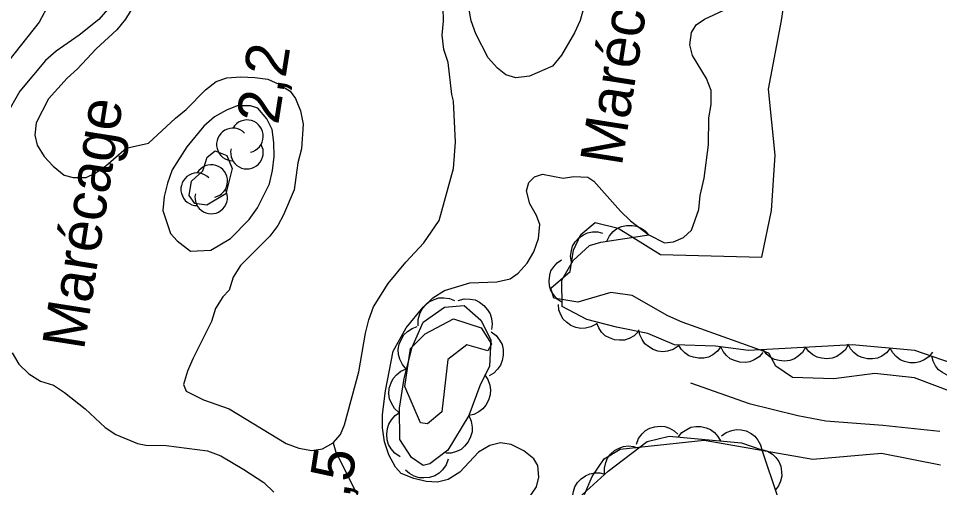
# Model space of a CAD drawing. Extents: x 282461 to 284471, y 5554090 to 5557646.
# Drawn here: x 283387.5 to 283452.6, y 5555299.8 to 5555332.9 of the extents above; entities that cross this region are included whole.
import ezdxf

# ---------------------------------------------------------------- set-up
doc = ezdxf.new("R2010")
doc.units = 0
for name, color, linetype in [('Niveau 2', 7, 'Continuous'), ('Niveau 22', 7, 'Continuous'), ('Niveau 3', 7, 'Continuous'), ('Niveau 4', 7, 'Continuous'), ('Niveau 44', 7, 'Continuous'), ('Niveau 7', 7, 'Continuous')]:
    doc.layers.add(name, color=color, linetype=linetype)

msp = doc.modelspace()

# ---------------------------------------------------------------- linework, layer by layer
at = {"layer": 'Niveau 2'}
for points in [[(283387.21, 5555348), (283388.34, 5555344.06), (283389.27, 5555342.21), (283389.76, 5555339.91), (283390.28, 5555336.74), (283389.69, 5555333.93), (283389.01, 5555332.65), (283385.14, 5555327.79)], [(283433.42, 5555311.91), (283430.9, 5555313.34), (283429.39, 5555313.55), (283427.06, 5555312.87), (283425.38, 5555313.15), (283425.15, 5555313.87), (283426.53, 5555315.03), (283426.77, 5555316.54), (283427.28, 5555317.66), (283428.28, 5555318.5), (283429.92, 5555318.1), (283432.9, 5555316.25), (283440.06, 5555316.05), (283440.76, 5555319.34), (283441, 5555323.25), (283440.53, 5555327.92), (283441.46, 5555332.77), (283442.2, 5555337.61)], [(283400.84, 5555319.72), (283400.01, 5555319.84), (283399.59, 5555320.41), (283399.77, 5555321.41), (283400.56, 5555322.14), (283400.87, 5555323.12), (283401.44, 5555323.56), (283402.26, 5555323.24), (283402.65, 5555322.32), (283402.2, 5555320.52), (283400.84, 5555319.72)], [(283416.44, 5555304.27), (283415.95, 5555304.34), (283414.83, 5555306.91), (283415.24, 5555309.6), (283416.28, 5555310.63), (283418.28, 5555311.69), (283420.24, 5555311.05), (283420.96, 5555309.9), (283420.71, 5555309.44), (283419.23, 5555309.85), (283417.87, 5555308.83), (283417.46, 5555305.13), (283416.44, 5555304.27)], [(283440.56, 5555309.27), (283434.43, 5555311.47), (283433.42, 5555311.91)], [(283471.91, 5555297.48), (283473.89, 5555297.67), (283474.58, 5555298.25), (283474.92, 5555299.07), (283474.33, 5555299.76), (283472.46, 5555300.32), (283463.13, 5555302.2), (283459.86, 5555303.32), (283456.23, 5555305.26), (283453.54, 5555306.51), (283450.85, 5555307.53), (283448.06, 5555307.84), (283445.15, 5555307.46), (283442.24, 5555307.55), (283441.07, 5555308.35), (283440.56, 5555309.27)], [(283427.53, 5555299.29), (283428.07, 5555300.57), (283428.93, 5555301.81), (283430.07, 5555302.5), (283435.99, 5555303.12), (283443.68, 5555301.78), (283448.53, 5555302.21), (283452.7, 5555301.38)]]:
    msp.add_lwpolyline(points, dxfattribs=at)
at = {"layer": 'Niveau 22'}
msp.add_lwpolyline([(283435.03, 5555307.18), (283439.18, 5555305.72), (283442.62, 5555304.88), (283444.6, 5555304.5), (283448.62, 5555304.19), (283452.64, 5555303.77)], dxfattribs=at)
at = {"layer": 'Niveau 4'}
for points in [[(283396.08, 5555334.51), (283395.11, 5555332.87), (283394.48, 5555332.11), (283393.04, 5555330.76), (283391.72, 5555329.35), (283390.97, 5555328.7), (283389.65, 5555327.23), (283388.8, 5555325.54), (283388.69, 5555324.67), (283388.87, 5555323.97), (283389.35, 5555323.16), (283390, 5555322.47), (283390.76, 5555321.84), (283391.4, 5555321.67), (283392.33, 5555321.68), (283392.97, 5555321.98), (283393.72, 5555322.51), (283395.16, 5555323.75), (283396.73, 5555324.11), (283398.63, 5555325.88), (283399.38, 5555326.47), (283400.76, 5555327.88), (283401.5, 5555328.47), (283402.26, 5555328.71), (283403.25, 5555328.78), (283404.24, 5555328.73)], [(283407.55, 5555323.71), (283407.27, 5555322.72), (283407.01, 5555320.8), (283406.27, 5555319.05), (283405.87, 5555318.29), (283405.3, 5555317.53), (283403.23, 5555315.47), (283402.71, 5555314.65), (283402.43, 5555313.72), (283401.97, 5555313.25), (283401.46, 5555312.43), (283401.18, 5555311.5), (283399.87, 5555308.87), (283399.48, 5555307.99), (283399.2, 5555307.06), (283399.38, 5555306.59), (283400.61, 5555305.97), (283402.42, 5555305.35), (283406.46, 5555302.89), (283407.34, 5555302.56), (283408.27, 5555302.39), (283409.03, 5555302.52), (283409.78, 5555302.93), (283410.29, 5555303.52), (283410.58, 5555304.22), (283411.58, 5555307.95), (283412.07, 5555310.68), (283412.29, 5555311.62), (283412.63, 5555312.55), (283413.66, 5555314.19), (283414.92, 5555315.71), (283416.19, 5555317.06), (283417.27, 5555318.64), (283418.28, 5555322.32), (283418.43, 5555324.18), (283418.28, 5555327.08), (283418.16, 5555327.54), (283417.9, 5555329.81), (283417.6, 5555330.73), (283417.47, 5555331.72), (283417.57, 5555332.71), (283417.56, 5555333.7)], [(283404.24, 5555328.73), (283405.17, 5555328.62), (283405.93, 5555328.28), (283406.75, 5555327.77), (283407.11, 5555327.25), (283407.46, 5555326.38), (283407.65, 5555325.45), (283407.55, 5555323.71)], [(283409.78, 5555302.93), (283409.96, 5555302.29), (283411.86, 5555298.54), (283412.46, 5555297.15), (283412.89, 5555295.76), (283413.08, 5555294.42), (283412.99, 5555292.33), (283412.35, 5555286.63), (283411.96, 5555285.4), (283410.88, 5555283.48), (283408.75, 5555280.95), (283407.26, 5555279.54), (283404.77, 5555278.3)]]:
    msp.add_lwpolyline(points, dxfattribs=at)
at = {"layer": 'Niveau 44'}
for points in [[(283429.12, 5555317.18), (283429.3, 5555317.56), (283429.57, 5555317.86), (283429.83, 5555318.07), (283430.15, 5555318.21), (283430.51, 5555318.3), (283430.9, 5555318.29), (283431.22, 5555318.25), (283431.54, 5555318.1), (283431.85, 5555317.89), (283432.09, 5555317.62)], [(283489.79, 5555302.45), (283483.29, 5555301.45), (283476.78, 5555301.15), (283470.5, 5555301.78), (283465.37, 5555303.11), (283454.15, 5555308.33), (283450.88, 5555309.46), (283446.46, 5555309.87), (283439.13, 5555309.46), (283436.8, 5555309.76), (283433.89, 5555309.87), (283432.02, 5555310.66), (283429.81, 5555311.1), (283427.71, 5555311.66), (283425.96, 5555312.56), (283425.93, 5555314.42), (283426.73, 5555315.82), (283427.88, 5555316.88), (283428.69, 5555317.12), (283432.09, 5555317.62)], [(283426.61, 5555315.71), (283426.55, 5555316.12), (283426.61, 5555316.53), (283426.7, 5555316.84), (283426.89, 5555317.14), (283427.14, 5555317.41), (283427.46, 5555317.62), (283427.75, 5555317.77), (283428.1, 5555317.83), (283428.47, 5555317.83), (283428.82, 5555317.75)], [(283425.96, 5555312.86), (283425.6, 5555313.09), (283425.34, 5555313.41), (283425.17, 5555313.69), (283425.07, 5555314.02), (283425.03, 5555314.39), (283425.09, 5555314.77), (283425.17, 5555315.09), (283425.36, 5555315.38), (283425.61, 5555315.66), (283425.91, 5555315.87)], [(283415.79, 5555311.21), (283415.79, 5555311.64), (283415.9, 5555312.04), (283416.04, 5555312.36), (283416.27, 5555312.64), (283416.56, 5555312.89), (283416.92, 5555313.06), (283417.24, 5555313.17), (283417.6, 5555313.18), (283417.99, 5555313.13), (283418.34, 5555313)], [(283418.62, 5555313), (283419.04, 5555313.11), (283419.46, 5555313.09), (283419.8, 5555313.04), (283420.12, 5555312.87), (283420.43, 5555312.65), (283420.69, 5555312.34), (283420.87, 5555312.06), (283420.97, 5555311.71), (283421.01, 5555311.32), (283420.96, 5555310.95)], [(283419.36, 5555304.86), (283417.87, 5555302.41), (283416.61, 5555301.46), (283416.14, 5555301.34), (283415.32, 5555301.91), (283414.49, 5555303.18), (283414.47, 5555305.39), (283414.79, 5555307.48), (283415.35, 5555309.7), (283416.14, 5555311.45), (283417.64, 5555312.51), (283419.03, 5555312.64), (283420.21, 5555311.61), (283420.92, 5555310.22), (283420.83, 5555308.36), (283420.15, 5555306.96), (283419.36, 5555304.86)], [(283428.36, 5555311.33), (283427.99, 5555311.12), (283427.6, 5555311.04), (283427.27, 5555311.02), (283426.92, 5555311.09), (283426.58, 5555311.23), (283426.27, 5555311.46), (283426.03, 5555311.68), (283425.86, 5555311.99), (283425.73, 5555312.34), (283425.69, 5555312.7)], [(283414.96, 5555308.13), (283414.67, 5555308.46), (283414.49, 5555308.84), (283414.39, 5555309.17), (283414.38, 5555309.53), (283414.44, 5555309.91), (283414.6, 5555310.27), (283414.77, 5555310.57), (283415.04, 5555310.81), (283415.37, 5555311.02), (283415.72, 5555311.15)], [(283431.34, 5555310.79), (283431.05, 5555310.5), (283430.69, 5555310.31), (283430.37, 5555310.2), (283430.02, 5555310.18), (283429.66, 5555310.22), (283429.3, 5555310.35), (283429.01, 5555310.5), (283428.75, 5555310.75), (283428.54, 5555311.05), (283428.4, 5555311.38)], [(283434.15, 5555309.76), (283433.8, 5555309.53), (283433.41, 5555309.42), (283433.08, 5555309.37), (283432.73, 5555309.42), (283432.38, 5555309.53), (283432.06, 5555309.74), (283431.8, 5555309.94), (283431.61, 5555310.24), (283431.45, 5555310.57), (283431.38, 5555310.93)], [(283420.95, 5555310.78), (283421.29, 5555310.52), (283421.54, 5555310.18), (283421.71, 5555309.88), (283421.78, 5555309.52), (283421.8, 5555309.14), (283421.71, 5555308.75), (283421.61, 5555308.43), (283421.39, 5555308.14), (283421.12, 5555307.87), (283420.8, 5555307.67)], [(283437.18, 5555309.75), (283436.93, 5555309.41), (283436.6, 5555309.16), (283436.31, 5555309), (283435.97, 5555308.93), (283435.6, 5555308.91), (283435.23, 5555308.99), (283434.91, 5555309.09), (283434.63, 5555309.29), (283434.37, 5555309.55), (283434.17, 5555309.86)], [(283440.15, 5555309.33), (283439.88, 5555309.01), (283439.53, 5555308.8), (283439.23, 5555308.67), (283438.88, 5555308.62), (283438.51, 5555308.64), (283438.14, 5555308.75), (283437.84, 5555308.87), (283437.57, 5555309.1), (283437.34, 5555309.39), (283437.17, 5555309.71)], [(283443.16, 5555309.69), (283442.95, 5555309.33), (283442.64, 5555309.05), (283442.37, 5555308.86), (283442.04, 5555308.76), (283441.67, 5555308.7), (283441.29, 5555308.75), (283440.97, 5555308.82), (283440.67, 5555308.99), (283440.38, 5555309.23), (283440.16, 5555309.52)], [(283446.16, 5555309.85), (283445.95, 5555309.49), (283445.64, 5555309.22), (283445.37, 5555309.03), (283445.04, 5555308.92), (283444.67, 5555308.87), (283444.29, 5555308.91), (283443.97, 5555308.98), (283443.67, 5555309.16), (283443.38, 5555309.4), (283443.16, 5555309.69)], [(283449.15, 5555309.62), (283448.89, 5555309.3), (283448.55, 5555309.07), (283448.25, 5555308.93), (283447.9, 5555308.87), (283447.53, 5555308.87), (283447.16, 5555308.97), (283446.86, 5555309.08), (283446.58, 5555309.31), (283446.34, 5555309.58), (283446.16, 5555309.9)], [(283452.14, 5555309.34), (283451.88, 5555309.02), (283451.54, 5555308.79), (283451.24, 5555308.65), (283450.9, 5555308.59), (283450.53, 5555308.59), (283450.16, 5555308.69), (283449.85, 5555308.81), (283449.57, 5555309.03), (283449.33, 5555309.3), (283449.15, 5555309.62)], [(283454.92, 5555308.06), (283454.59, 5555307.81), (283454.2, 5555307.67), (283453.88, 5555307.6), (283453.53, 5555307.63), (283453.17, 5555307.72), (283452.83, 5555307.9), (283452.56, 5555308.09), (283452.35, 5555308.37), (283452.17, 5555308.7), (283452.08, 5555309.05)], [(283414.42, 5555305.07), (283414.1, 5555305.37), (283413.89, 5555305.73), (283413.76, 5555306.05), (283413.72, 5555306.41), (283413.74, 5555306.79), (283413.87, 5555307.17), (283414.01, 5555307.48), (283414.25, 5555307.75), (283414.55, 5555307.99), (283414.89, 5555308.15)], [(283420.46, 5555307.77), (283420.71, 5555307.42), (283420.84, 5555307.02), (283420.9, 5555306.68), (283420.87, 5555306.32), (283420.76, 5555305.95), (283420.56, 5555305.61), (283420.36, 5555305.33), (283420.07, 5555305.12), (283419.72, 5555304.95), (283419.36, 5555304.86)], [(283414.5, 5555301.96), (283414.14, 5555302.2), (283413.87, 5555302.52), (283413.69, 5555302.81), (283413.59, 5555303.16), (283413.56, 5555303.55), (283413.62, 5555303.94), (283413.71, 5555304.26), (283413.91, 5555304.57), (283414.17, 5555304.86), (283414.47, 5555305.07)], [(283419.36, 5555304.86), (283419.54, 5555304.47), (283419.6, 5555304.05), (283419.6, 5555303.71), (283419.49, 5555303.36), (283419.32, 5555303.01), (283419.06, 5555302.71), (283418.82, 5555302.48), (283418.49, 5555302.33), (283418.12, 5555302.22), (283417.74, 5555302.2)], [(283431.22, 5555302.85), (283431.36, 5555303.25), (283431.61, 5555303.57), (283431.85, 5555303.8), (283432.16, 5555303.97), (283432.51, 5555304.08), (283432.89, 5555304.11), (283433.22, 5555304.09), (283433.55, 5555303.97), (283433.87, 5555303.79), (283434.14, 5555303.54)], [(283434.15, 5555303.34), (283434.42, 5555303.67), (283434.76, 5555303.89), (283435.05, 5555304.04), (283435.4, 5555304.1), (283435.77, 5555304.1), (283436.14, 5555304), (283436.45, 5555303.89), (283436.72, 5555303.67), (283436.97, 5555303.39), (283437.15, 5555303.07)], [(283437.22, 5555303.43), (283437.56, 5555303.68), (283437.94, 5555303.82), (283438.26, 5555303.89), (283438.61, 5555303.86), (283438.97, 5555303.78), (283439.31, 5555303.59), (283439.58, 5555303.41), (283439.79, 5555303.13), (283439.97, 5555302.8), (283440.06, 5555302.45)], [(283426.63, 5555298.58), (283429.21, 5555300.93), (283431.96, 5555303.03), (283433.53, 5555303.4), (283438.64, 5555302.94), (283440.07, 5555302.45), (283441.18, 5555299.16)], [(283428.96, 5555300.74), (283428.94, 5555301.16), (283429.04, 5555301.56), (283429.16, 5555301.86), (283429.37, 5555302.14), (283429.65, 5555302.39), (283429.98, 5555302.57), (283430.29, 5555302.69), (283430.64, 5555302.72), (283431.01, 5555302.68), (283431.35, 5555302.57)], [(283440.07, 5555302.46), (283440.47, 5555302.35), (283440.82, 5555302.13), (283441.07, 5555301.91), (283441.26, 5555301.62), (283441.41, 5555301.28), (283441.47, 5555300.9), (283441.49, 5555300.58), (283441.4, 5555300.24), (283441.25, 5555299.9), (283441.03, 5555299.61)], [(283417.9, 5555301.79), (283417.76, 5555301.38), (283417.5, 5555301.04), (283417.27, 5555300.8), (283416.95, 5555300.62), (283416.58, 5555300.49), (283416.19, 5555300.46), (283415.85, 5555300.47), (283415.51, 5555300.59), (283415.17, 5555300.77), (283414.89, 5555301.02)], [(283426.76, 5555298.7), (283426.7, 5555299.11), (283426.76, 5555299.51), (283426.85, 5555299.83), (283427.04, 5555300.13), (283427.3, 5555300.4), (283427.62, 5555300.61), (283427.91, 5555300.75), (283428.26, 5555300.81), (283428.63, 5555300.81), (283428.98, 5555300.72)]]:
    msp.add_lwpolyline(points, dxfattribs=at)
for centre, start, end in [((283402.693, 5555324.011), 44.11537, 269.80396), ((283403.685, 5555324.588), 282.26917, 149.72625), ((283403.685, 5555323.434), 166.93686, 29.62122), ((283401.164, 5555321.425), 282.26917, 149.72625), ((283400.171, 5555320.848), 44.11537, 269.80396), ((283401.164, 5555320.271), 166.93686, 29.62122)]:
    msp.add_arc(centre, 1.154, start, end, dxfattribs=at)
at = {"layer": 'Niveau 7'}
for points in [[(283427.5, 5555333.7), (283427.22, 5555332.77), (283426.83, 5555331.89), (283425.91, 5555330.32), (283425.28, 5555329.55), (283423.66, 5555328.84), (283422.68, 5555328.71), (283421.97, 5555328.94), (283421.39, 5555329.39), (283420.74, 5555330.14), (283419.85, 5555331.82), (283419.54, 5555332.74), (283419.36, 5555333.67)], [(283424.58, 5555321.91), (283426.04, 5555321.63), (283426.79, 5555321.76), (283427.78, 5555321.71), (283428.2, 5555321.43), (283430.08, 5555319.3), (283430.79, 5555318.61), (283432.09, 5555317.62), (283433.19, 5555317.06), (283433.83, 5555317.13), (283434.53, 5555317.43), (283435.1, 5555317.96), (283435.61, 5555319.41), (283435.71, 5555320.4), (283435.99, 5555321.63), (283436.29, 5555323.98), (283436.32, 5555325.9), (283436.49, 5555326.83), (283436.48, 5555327.82), (283436.17, 5555328.68), (283435.17, 5555330.3), (283434.98, 5555331.05), (283435.09, 5555331.93), (283435.43, 5555332.45), (283436.01, 5555332.87), (283437.69, 5555333.64)], [(283393.84, 5555333.55), (283393.21, 5555332.84), (283391.83, 5555331.72), (283390.21, 5555330.6), (283389.46, 5555329.95), (283387.63, 5555327.78), (283386.66, 5555326.09)], [(283401.14, 5555316.54), (283402.53, 5555317.37), (283403.85, 5555318.72), (283404.42, 5555319.54), (283405.27, 5555321.23), (283405.5, 5555322.17), (283405.6, 5555323.16), (283405.59, 5555324.14), (283405.46, 5555325.07), (283405.1, 5555325.82), (283404.45, 5555326.57), (283403.93, 5555326.74), (283403, 5555326.73), (283402.25, 5555326.43), (283401.38, 5555325.96), (283400.63, 5555325.31), (283399.43, 5555323.84), (283398.4, 5555322.21), (283398.06, 5555321.27), (283397.84, 5555320.34), (283397.73, 5555319.35), (283398.28, 5555317.73), (283398.75, 5555317.21), (283399.69, 5555316.47), (283401.14, 5555316.54)], [(283423.57, 5555299.01), (283424.14, 5555299.83), (283424.31, 5555300.52), (283424.24, 5555301.34), (283423.95, 5555301.8), (283423.24, 5555302.37), (283422.36, 5555302.83), (283421.6, 5555302.94), (283420.85, 5555302.75), (283420.04, 5555302.28), (283418.72, 5555300.87), (283417.91, 5555300.34), (283417.16, 5555300.16), (283416.34, 5555300.21), (283415.47, 5555300.43), (283414.59, 5555300.77), (283414.18, 5555301.23), (283413.7, 5555302.1), (283413.4, 5555303.02), (283413.27, 5555304.01), (283413.26, 5555304.94), (283413.47, 5555306.62), (283414.02, 5555309.42), (283414.93, 5555311.06), (283416.14, 5555312.52), (283416.83, 5555313.17), (283417.64, 5555313.7), (283419.44, 5555314.24), (283421.35, 5555314.32), (283422.28, 5555314.51), (283422.86, 5555314.92), (283423.49, 5555315.62), (283423.95, 5555316.44), (283424.29, 5555317.37), (283424.39, 5555318.36), (283424.15, 5555319), (283423.68, 5555319.81), (283423.43, 5555320.73), (283423.6, 5555321.32), (283424, 5555321.73), (283424.58, 5555321.91)], [(283387.09, 5555309.3), (283387.56, 5555308.5), (283388.27, 5555307.81), (283389.09, 5555307.29), (283390.02, 5555307.01), (283390.79, 5555306.5), (283392.25, 5555305.35), (283393.66, 5555304.03), (283394.43, 5555303.52), (283395.95, 5555302.89), (283396.53, 5555302.78), (283397.98, 5555302.74), (283400.9, 5555302.37), (283401.83, 5555302.03), (283403.47, 5555301.06), (283404.88, 5555300.14), (283405.59, 5555299.45)]]:
    msp.add_lwpolyline(points, dxfattribs=at)

# ---------------------------------------------------------------- texts
at = {"layer": 'Niveau 3'}
for s, rotation, p in [('    2,2', 81.0958, (283405.2, 5555320.95)), ('2,5  ', 81.09575, (283410.58, 5555296.79))]:
    msp.add_text(s, height=3, rotation=rotation, dxfattribs=at).set_placement(p)
at = {"layer": 'Niveau 7'}
for p in [(283430.17, 5555322.42), (283392.16, 5555309.43)]:
    msp.add_text('Marécage', height=3, rotation=81.0598, dxfattribs=at).set_placement(p)

doc.saveas('drawing.dxf')
